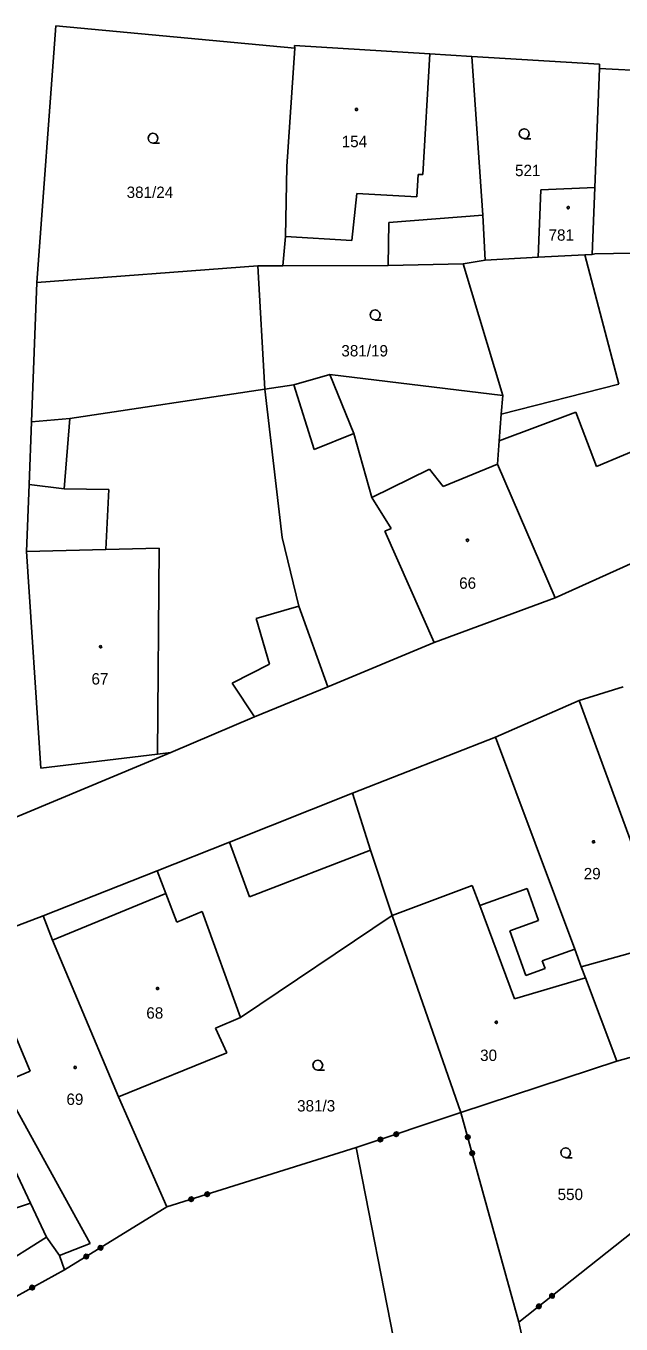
# Model space of a CAD drawing. Extents: x -757994 to -755874, y -1047691 to -1046119.
# Drawn here: x -757585.5 to -757541.1, y -1047173.7 to -1047076.8 of the extents above; entities that cross this region are included whole.
import ezdxf

# ---------------------------------------------------------------- set-up
doc = ezdxf.new("R2010")
doc.units = 0
doc.layers.add('katastrální mapa', color=7, linetype='Continuous')

msp = doc.modelspace()

# ---------------------------------------------------------------- linework, layer by layer
at = {"layer": 'katastrální mapa'}
for p, q in [((-757583.31, -1047076.76), (-757584.71, -1047095.92)), ((-757565.47, -1047078.42), (-757583.31, -1047076.76)), ((-757565.49, -1047078.21), (-757565.47, -1047078.42)), ((-757565.49, -1047078.21), (-757555.39, -1047078.84)), ((-757565.47, -1047078.42), (-757566.07, -1047087.26)), ((-757555.39, -1047078.84), (-757555.93, -1047087.86)), ((-757555.39, -1047078.84), (-757552.27, -1047079.03)), ((-757552.27, -1047079.03), (-757542.74, -1047079.6)), ((-757551.44, -1047090.88), (-757552.27, -1047079.03)), ((-757543.1, -1047088.83), (-757542.75, -1047079.94)), ((-757542.74, -1047079.6), (-757542.75, -1047079.94)), ((-757532.72, -1047080.42), (-757542.75, -1047079.94)), ((-757566.07, -1047087.26), (-757566.18, -1047092.47)), ((-757556.27, -1047087.84), (-757556.36, -1047089.52)), ((-757555.93, -1047087.86), (-757556.27, -1047087.84)), ((-757547.32, -1047094.03), (-757547.13, -1047088.99)), ((-757547.13, -1047088.99), (-757543.1, -1047088.83)), ((-757543.29, -1047093.81), (-757543.1, -1047088.83)), ((-757560.84, -1047089.26), (-757561.21, -1047092.78)), ((-757556.36, -1047089.52), (-757560.84, -1047089.26)), ((-757551.44, -1047090.88), (-757558.46, -1047091.43)), ((-757551.26, -1047094.24), (-757551.44, -1047090.88)), ((-757558.46, -1047091.43), (-757558.5, -1047094.64)), ((-757566.18, -1047092.47), (-757566.37, -1047094.66)), ((-757561.21, -1047092.78), (-757566.18, -1047092.47)), ((-757547.32, -1047094.03), (-757543.84, -1047093.84)), ((-757543.84, -1047093.84), (-757543.29, -1047093.81)), ((-757541.29, -1047103.51), (-757543.84, -1047093.84)), ((-757543.09, -1047093.78), (-757543.29, -1047093.81)), ((-757536.21, -1047093.62), (-757543.09, -1047093.78)), ((-757584.71, -1047095.92), (-757568.22, -1047094.67)), ((-757566.37, -1047094.66), (-757568.22, -1047094.67)), ((-757568.22, -1047094.67), (-757567.7, -1047103.86)), ((-757558.5, -1047094.64), (-757566.37, -1047094.66)), ((-757552.91, -1047094.52), (-757558.5, -1047094.64)), ((-757551.26, -1047094.24), (-757552.91, -1047094.52)), ((-757552.91, -1047094.52), (-757549.96, -1047104.34)), ((-757547.32, -1047094.03), (-757551.26, -1047094.24)), ((-757584.71, -1047095.92), (-757585.12, -1047106.31)), ((-757565.55, -1047103.54), (-757567.7, -1047103.86)), ((-757562.87, -1047102.77), (-757565.55, -1047103.54)), ((-757565.55, -1047103.54), (-757564.03, -1047108.37)), ((-757561.08, -1047107.18), (-757562.87, -1047102.77)), ((-757562.87, -1047102.77), (-757549.96, -1047104.34)), ((-757550.07, -1047105.75), (-757541.29, -1047103.51)), ((-757582.26, -1047106.05), (-757567.7, -1047103.86)), ((-757567.7, -1047103.86), (-757566.42, -1047114.94)), ((-757549.96, -1047104.34), (-757550.07, -1047105.75)), ((-757585.12, -1047106.31), (-757585.3, -1047111)), ((-757585.12, -1047106.31), (-757582.26, -1047106.05)), ((-757582.68, -1047111.31), (-757582.26, -1047106.05)), ((-757544.51, -1047105.59), (-757550.22, -1047107.72)), ((-757550.07, -1047105.75), (-757550.22, -1047107.72)), ((-757544.51, -1047105.59), (-757542.96, -1047109.64)), ((-757542.96, -1047109.64), (-757535.34, -1047106.44)), ((-757564.03, -1047108.37), (-757561.08, -1047107.18)), ((-757559.73, -1047111.95), (-757561.08, -1047107.18)), ((-757550.22, -1047107.72), (-757550.36, -1047109.46)), ((-757555.42, -1047109.84), (-757559.73, -1047111.95)), ((-757554.4, -1047111.14), (-757555.42, -1047109.84)), ((-757550.36, -1047109.46), (-757554.4, -1047111.14)), ((-757550.36, -1047109.46), (-757546.05, -1047119.45)), ((-757585.3, -1047111), (-757585.5, -1047116)), ((-757582.68, -1047111.31), (-757585.3, -1047111)), ((-757579.35, -1047111.36), (-757582.68, -1047111.31)), ((-757579.58, -1047115.84), (-757579.35, -1047111.36)), ((-757559.73, -1047111.95), (-757558.29, -1047114.26)), ((-757529.67, -1047112.06), (-757546.05, -1047119.45)), ((-757566.42, -1047114.94), (-757565.18, -1047120.07)), ((-757558.29, -1047114.26), (-757558.75, -1047114.46)), ((-757558.75, -1047114.46), (-757555.08, -1047122.77)), ((-757579.58, -1047115.84), (-757585.5, -1047116)), ((-757585.5, -1047116), (-757584.43, -1047132.15)), ((-757575.6, -1047115.73), (-757579.58, -1047115.84)), ((-757575.72, -1047131.12), (-757575.6, -1047115.73)), ((-757546.05, -1047119.45), (-757555.08, -1047122.77)), ((-757565.18, -1047120.07), (-757568.35, -1047121)), ((-757568.35, -1047121), (-757567.37, -1047124.41)), ((-757565.18, -1047120.07), (-757563.02, -1047126.09)), ((-757555.08, -1047122.77), (-757563.02, -1047126.09)), ((-757567.37, -1047124.41), (-757570.15, -1047125.82)), ((-757570.15, -1047125.82), (-757568.47, -1047128.34)), ((-757563.02, -1047126.09), (-757568.47, -1047128.34)), ((-757540.98, -1047126.09), (-757544.26, -1047127.12)), ((-757544.26, -1047127.12), (-757550.5, -1047129.84)), ((-757544.26, -1047127.12), (-757539.01, -1047141.42)), ((-757568.47, -1047128.34), (-757574.73, -1047131)), ((-757550.5, -1047129.84), (-757561.18, -1047134.04)), ((-757550.5, -1047129.84), (-757544.58, -1047145.67)), ((-757574.73, -1047131), (-757592.4, -1047138.36)), ((-757584.43, -1047132.15), (-757575.72, -1047131.12)), ((-757575.72, -1047131.12), (-757574.73, -1047131)), ((-757561.18, -1047134.04), (-757570.34, -1047137.69)), ((-757559.83, -1047138.29), (-757561.18, -1047134.04)), ((-757570.34, -1047137.69), (-757575.74, -1047139.82)), ((-757568.85, -1047141.76), (-757570.34, -1047137.69)), ((-757559.83, -1047138.29), (-757568.85, -1047141.76)), ((-757558.21, -1047143.16), (-757559.83, -1047138.29)), ((-757575.74, -1047139.82), (-757584.26, -1047143.18)), ((-757575.74, -1047139.82), (-757575.09, -1047141.52)), ((-757552.23, -1047140.92), (-757558.21, -1047143.16)), ((-757552.23, -1047140.92), (-757551.67, -1047142.42)), ((-757551.67, -1047142.42), (-757548.15, -1047141.15)), ((-757548.15, -1047141.15), (-757547.29, -1047143.53)), ((-757583.54, -1047145.01), (-757575.09, -1047141.52)), ((-757575.09, -1047141.52), (-757574.27, -1047143.65)), ((-757584.26, -1047143.18), (-757589.29, -1047145.09)), ((-757583.54, -1047145.01), (-757584.26, -1047143.18)), ((-757574.27, -1047143.65), (-757572.39, -1047142.85)), ((-757572.39, -1047142.85), (-757569.52, -1047150.77)), ((-757569.52, -1047150.77), (-757558.21, -1047143.16)), ((-757553.08, -1047157.87), (-757558.21, -1047143.16)), ((-757551.67, -1047142.42), (-757549.08, -1047149.39)), ((-757547.29, -1047143.53), (-757549.43, -1047144.3)), ((-757585.21, -1047154.77), (-757589.29, -1047145.09)), ((-757578.64, -1047156.7), (-757583.54, -1047145.01)), ((-757549.43, -1047144.3), (-757548.23, -1047147.63)), ((-757544.1, -1047146.98), (-757537.63, -1047145.17)), ((-757547.01, -1047146.55), (-757544.58, -1047145.67)), ((-757544.58, -1047145.67), (-757544.1, -1047146.98)), ((-757548.23, -1047147.63), (-757546.8, -1047147.12)), ((-757546.8, -1047147.12), (-757547.01, -1047146.55)), ((-757543.78, -1047147.82), (-757544.1, -1047146.98)), ((-757543.78, -1047147.82), (-757549.08, -1047149.39)), ((-757541.46, -1047154.03), (-757543.78, -1047147.82)), ((-757571.39, -1047151.57), (-757569.52, -1047150.77)), ((-757541.46, -1047154.03), (-757530.12, -1047150.9)), ((-757570.55, -1047153.41), (-757571.39, -1047151.57)), ((-757548.75, -1047173.51), (-757521.83, -1047152.14)), ((-757578.64, -1047156.7), (-757570.55, -1047153.41)), ((-757589.05, -1047156.39), (-757585.21, -1047154.77)), ((-757553.08, -1047157.87), (-757541.46, -1047154.03)), ((-757586.95, -1047156.34), (-757580.75, -1047167.65)), ((-757575.01, -1047164.9), (-757578.64, -1047156.7)), ((-757585.19, -1047164.63), (-757588.7, -1047157.2)), ((-757560.89, -1047160.48), (-757553.08, -1047157.87)), ((-757553.08, -1047157.87), (-757548.75, -1047173.51)), ((-757575.01, -1047164.9), (-757560.89, -1047160.48)), ((-757560.89, -1047160.48), (-757553.01, -1047200.67)), ((-757589.11, -1047165.96), (-757585.19, -1047164.63)), ((-757583.99, -1047167.16), (-757585.19, -1047164.63)), ((-757582.65, -1047169.61), (-757575.01, -1047164.9)), ((-757588.96, -1047170.3), (-757583.99, -1047167.16)), ((-757583.04, -1047168.54), (-757583.99, -1047167.16)), ((-757580.75, -1047167.65), (-757583.04, -1047168.54)), ((-757582.65, -1047169.61), (-757583.04, -1047168.54)), ((-757587.83, -1047172.45), (-757582.65, -1047169.61)), ((-757548.75, -1047173.51), (-757545.43, -1047188.81))]:
    msp.add_line(p, q, dxfattribs=at)
for points in [[(-757560.88, -1047082.905), (-757560.83, -1047082.915), (-757560.805, -1047082.96), (-757560.795, -1047082.99), (-757560.805, -1047083.035), (-757560.845, -1047083.07), (-757560.88, -1047083.075), (-757560.925, -1047083.06), (-757560.955, -1047083.03), (-757560.965, -1047082.99), (-757560.955, -1047082.945), (-757560.915, -1047082.91)], [(-757545.08, -1047090.235), (-757545.03, -1047090.245), (-757545.005, -1047090.29), (-757544.995, -1047090.32), (-757545.005, -1047090.365), (-757545.045, -1047090.4), (-757545.08, -1047090.405), (-757545.125, -1047090.39), (-757545.155, -1047090.36), (-757545.165, -1047090.32), (-757545.155, -1047090.275), (-757545.115, -1047090.24)], [(-757552.6, -1047115.065), (-757552.55, -1047115.075), (-757552.525, -1047115.12), (-757552.515, -1047115.15), (-757552.525, -1047115.195), (-757552.565, -1047115.23), (-757552.6, -1047115.235), (-757552.645, -1047115.22), (-757552.675, -1047115.19), (-757552.685, -1047115.15), (-757552.675, -1047115.105), (-757552.635, -1047115.07)], [(-757579.96, -1047123.015), (-757579.91, -1047123.025), (-757579.885, -1047123.07), (-757579.875, -1047123.1), (-757579.885, -1047123.145), (-757579.925, -1047123.18), (-757579.96, -1047123.185), (-757580.005, -1047123.17), (-757580.035, -1047123.14), (-757580.045, -1047123.1), (-757580.035, -1047123.055), (-757579.995, -1047123.02)], [(-757543.18, -1047137.575), (-757543.13, -1047137.585), (-757543.105, -1047137.63), (-757543.095, -1047137.66), (-757543.105, -1047137.705), (-757543.145, -1047137.74), (-757543.18, -1047137.745), (-757543.225, -1047137.73), (-757543.255, -1047137.7), (-757543.265, -1047137.66), (-757543.255, -1047137.615), (-757543.215, -1047137.58)], [(-757575.71, -1047148.525), (-757575.66, -1047148.535), (-757575.635, -1047148.58), (-757575.625, -1047148.61), (-757575.635, -1047148.655), (-757575.675, -1047148.69), (-757575.71, -1047148.695), (-757575.755, -1047148.68), (-757575.785, -1047148.65), (-757575.795, -1047148.61), (-757575.785, -1047148.565), (-757575.745, -1047148.53)], [(-757550.44, -1047151.045), (-757550.39, -1047151.055), (-757550.365, -1047151.1), (-757550.355, -1047151.13), (-757550.365, -1047151.175), (-757550.405, -1047151.21), (-757550.44, -1047151.215), (-757550.485, -1047151.2), (-757550.515, -1047151.17), (-757550.525, -1047151.13), (-757550.515, -1047151.085), (-757550.475, -1047151.05)], [(-757581.87, -1047154.415), (-757581.82, -1047154.425), (-757581.795, -1047154.47), (-757581.785, -1047154.5), (-757581.795, -1047154.545), (-757581.835, -1047154.58), (-757581.87, -1047154.585), (-757581.915, -1047154.57), (-757581.945, -1047154.54), (-757581.955, -1047154.5), (-757581.945, -1047154.455), (-757581.905, -1047154.42)]]:
    msp.add_lwpolyline(points, close=True, dxfattribs=at)
for points in [[(-757576.05, -1047085.51), (-757576.24, -1047085.46), (-757576.375, -1047085.325), (-757576.425, -1047085.14), (-757576.375, -1047084.955), (-757576.24, -1047084.82), (-757576.055, -1047084.77), (-757575.87, -1047084.82), (-757575.735, -1047084.955), (-757575.685, -1047085.145), (-757575.735, -1047085.335), (-757575.87, -1047085.47), (-757576.06, -1047085.52), (-757575.56, -1047085.52)], [(-757548.35, -1047085.17), (-757548.54, -1047085.12), (-757548.675, -1047084.985), (-757548.725, -1047084.8), (-757548.675, -1047084.615), (-757548.54, -1047084.48), (-757548.355, -1047084.43), (-757548.17, -1047084.48), (-757548.035, -1047084.615), (-757547.985, -1047084.805), (-757548.035, -1047084.995), (-757548.17, -1047085.13), (-757548.36, -1047085.18), (-757547.86, -1047085.18)], [(-757559.48, -1047098.7), (-757559.67, -1047098.65), (-757559.805, -1047098.515), (-757559.855, -1047098.33), (-757559.805, -1047098.145), (-757559.67, -1047098.01), (-757559.485, -1047097.96), (-757559.3, -1047098.01), (-757559.165, -1047098.145), (-757559.115, -1047098.335), (-757559.165, -1047098.525), (-757559.3, -1047098.66), (-757559.49, -1047098.71), (-757558.99, -1047098.71)], [(-757563.76, -1047154.7), (-757563.95, -1047154.65), (-757564.085, -1047154.515), (-757564.135, -1047154.33), (-757564.085, -1047154.145), (-757563.95, -1047154.01), (-757563.765, -1047153.96), (-757563.58, -1047154.01), (-757563.445, -1047154.145), (-757563.395, -1047154.335), (-757563.445, -1047154.525), (-757563.58, -1047154.66), (-757563.77, -1047154.71), (-757563.27, -1047154.71)], [(-757559.077, -1047159.706), (-757558.957, -1047159.766), (-757558.914, -1047159.894), (-757558.974, -1047160.014), (-757559.102, -1047160.057), (-757559.222, -1047159.997), (-757559.265, -1047159.869), (-757559.205, -1047159.749), (-757559.077, -1047159.706), (-757559.075, -1047159.726), (-757559.189, -1047159.764), (-757559.214, -1047159.815), (-757559.025, -1047159.751), (-757558.974, -1047159.777), (-757559.24, -1047159.866), (-757559.227, -1047159.904), (-757558.961, -1047159.815), (-757558.949, -1047159.853), (-757559.214, -1047159.941), (-757559.202, -1047159.979), (-757558.936, -1047159.891), (-757558.961, -1047159.941), (-757559.151, -1047160.005), (-757559.1, -1047160.03), (-757558.987, -1047159.992)], [(-757557.892, -1047159.309), (-757557.771, -1047159.369), (-757557.729, -1047159.497), (-757557.789, -1047159.617), (-757557.917, -1047159.66), (-757558.037, -1047159.6), (-757558.08, -1047159.472), (-757558.02, -1047159.352), (-757557.892, -1047159.309), (-757557.9, -1047159.333), (-757558.013, -1047159.371), (-757558.039, -1047159.421), (-757557.849, -1047159.358), (-757557.798, -1047159.383), (-757558.064, -1047159.472), (-757558.051, -1047159.51), (-757557.786, -1047159.421), (-757557.773, -1047159.459), (-757558.038, -1047159.548), (-757558.026, -1047159.586), (-757557.76, -1047159.497), (-757557.785, -1047159.548), (-757557.975, -1047159.611), (-757557.924, -1047159.636), (-757557.811, -1047159.598)], [(-757552.401, -1047159.721), (-757552.468, -1047159.838), (-757552.598, -1047159.874), (-757552.714, -1047159.808), (-757552.75, -1047159.678), (-757552.684, -1047159.561), (-757552.554, -1047159.525), (-757552.437, -1047159.591), (-757552.401, -1047159.721), (-757552.422, -1047159.722), (-757552.454, -1047159.606), (-757552.503, -1047159.578), (-757552.45, -1047159.771), (-757552.478, -1047159.82), (-757552.552, -1047159.55), (-757552.591, -1047159.561), (-757552.516, -1047159.831), (-757552.555, -1047159.841), (-757552.629, -1047159.571), (-757552.668, -1047159.582), (-757552.593, -1047159.852), (-757552.643, -1047159.824), (-757552.696, -1047159.631), (-757552.724, -1047159.681), (-757552.692, -1047159.796)], [(-757552.068, -1047160.926), (-757552.135, -1047161.043), (-757552.265, -1047161.079), (-757552.382, -1047161.012), (-757552.418, -1047160.882), (-757552.351, -1047160.765), (-757552.221, -1047160.73), (-757552.104, -1047160.796), (-757552.068, -1047160.926), (-757552.092, -1047160.917), (-757552.124, -1047160.801), (-757552.173, -1047160.773), (-757552.119, -1047160.966), (-757552.147, -1047161.015), (-757552.222, -1047160.745), (-757552.261, -1047160.756), (-757552.186, -1047161.026), (-757552.224, -1047161.037), (-757552.299, -1047160.767), (-757552.338, -1047160.777), (-757552.263, -1047161.047), (-757552.312, -1047161.019), (-757552.366, -1047160.826), (-757552.393, -1047160.876), (-757552.361, -1047160.991)], [(-757545.26, -1047161.23), (-757545.45, -1047161.18), (-757545.585, -1047161.045), (-757545.635, -1047160.86), (-757545.585, -1047160.675), (-757545.45, -1047160.54), (-757545.265, -1047160.49), (-757545.08, -1047160.54), (-757544.945, -1047160.675), (-757544.895, -1047160.865), (-757544.945, -1047161.055), (-757545.08, -1047161.19), (-757545.27, -1047161.24), (-757544.77, -1047161.24)], [(-757573.183, -1047164.16), (-757573.064, -1047164.222), (-757573.023, -1047164.351), (-757573.086, -1047164.47), (-757573.214, -1047164.511), (-757573.333, -1047164.448), (-757573.374, -1047164.319), (-757573.311, -1047164.2), (-757573.183, -1047164.16), (-757573.181, -1047164.181), (-757573.296, -1047164.216), (-757573.322, -1047164.267), (-757573.131, -1047164.207), (-757573.081, -1047164.233), (-757573.348, -1047164.317), (-757573.336, -1047164.355), (-757573.069, -1047164.271), (-757573.057, -1047164.31), (-757573.324, -1047164.393), (-757573.313, -1047164.431), (-757573.045, -1047164.348), (-757573.072, -1047164.398), (-757573.262, -1047164.457), (-757573.212, -1047164.484), (-757573.098, -1047164.448)], [(-757571.989, -1047163.787), (-757571.87, -1047163.849), (-757571.83, -1047163.978), (-757571.892, -1047164.097), (-757572.021, -1047164.138), (-757572.14, -1047164.075), (-757572.181, -1047163.946), (-757572.118, -1047163.827), (-757571.989, -1047163.787), (-757571.998, -1047163.811), (-757572.112, -1047163.846), (-757572.139, -1047163.897), (-757571.948, -1047163.837), (-757571.898, -1047163.863), (-757572.165, -1047163.947), (-757572.153, -1047163.985), (-757571.886, -1047163.901), (-757571.874, -1047163.94), (-757572.141, -1047164.023), (-757572.129, -1047164.061), (-757571.862, -1047163.978), (-757571.888, -1047164.028), (-757572.079, -1047164.087), (-757572.029, -1047164.114), (-757571.914, -1047164.078)], [(-757581.061, -1047168.442), (-757580.931, -1047168.473), (-757580.86, -1047168.588), (-757580.891, -1047168.719), (-757581.006, -1047168.79), (-757581.137, -1047168.759), (-757581.207, -1047168.644), (-757581.176, -1047168.513), (-757581.061, -1047168.442), (-757581.055, -1047168.462), (-757581.157, -1047168.525), (-757581.17, -1047168.58), (-757581, -1047168.475), (-757580.945, -1047168.488), (-757581.183, -1047168.635), (-757581.162, -1047168.669), (-757580.924, -1047168.522), (-757580.903, -1047168.556), (-757581.142, -1047168.703), (-757581.121, -1047168.737), (-757580.882, -1047168.59), (-757580.895, -1047168.645), (-757581.066, -1047168.75), (-757581.01, -1047168.763), (-757580.908, -1047168.7)], [(-757579.997, -1047167.787), (-757579.866, -1047167.818), (-757579.796, -1047167.933), (-757579.827, -1047168.064), (-757579.942, -1047168.134), (-757580.072, -1047168.103), (-757580.143, -1047167.988), (-757580.112, -1047167.858), (-757579.997, -1047167.787), (-757579.999, -1047167.812), (-757580.101, -1047167.875), (-757580.115, -1047167.93), (-757579.944, -1047167.825), (-757579.889, -1047167.838), (-757580.128, -1047167.985), (-757580.107, -1047168.019), (-757579.868, -1047167.872), (-757579.847, -1047167.906), (-757580.086, -1047168.053), (-757580.065, -1047168.087), (-757579.826, -1047167.94), (-757579.839, -1047167.995), (-757580.01, -1047168.1), (-757579.955, -1047168.113), (-757579.852, -1047168.05)], [(-757585.088, -1047170.764), (-757584.959, -1047170.801), (-757584.894, -1047170.92), (-757584.932, -1047171.049), (-757585.05, -1047171.114), (-757585.179, -1047171.076), (-757585.244, -1047170.958), (-757585.206, -1047170.829), (-757585.088, -1047170.764), (-757585.092, -1047170.789), (-757585.197, -1047170.846), (-757585.213, -1047170.901), (-757585.037, -1047170.804), (-757584.983, -1047170.82), (-757585.228, -1047170.955), (-757585.209, -1047170.99), (-757584.964, -1047170.855), (-757584.944, -1047170.89), (-757585.19, -1047171.025), (-757585.171, -1047171.06), (-757584.925, -1047170.925), (-757584.941, -1047170.98), (-757585.116, -1047171.076), (-757585.062, -1047171.092), (-757584.957, -1047171.034)], [(-757546.331, -1047171.386), (-757546.198, -1047171.401), (-757546.114, -1047171.507), (-757546.129, -1047171.64), (-757546.235, -1047171.724), (-757546.369, -1047171.709), (-757546.453, -1047171.603), (-757546.437, -1047171.47), (-757546.331, -1047171.386), (-757546.331, -1047171.411), (-757546.425, -1047171.485), (-757546.431, -1047171.542), (-757546.275, -1047171.417), (-757546.218, -1047171.424), (-757546.438, -1047171.598), (-757546.413, -1047171.629), (-757546.193, -1047171.455), (-757546.169, -1047171.486), (-757546.388, -1047171.66), (-757546.363, -1047171.692), (-757546.144, -1047171.518), (-757546.15, -1047171.574), (-757546.307, -1047171.698), (-757546.251, -1047171.705), (-757546.157, -1047171.63)], [(-757547.31, -1047172.163), (-757547.177, -1047172.178), (-757547.093, -1047172.284), (-757547.108, -1047172.418), (-757547.214, -1047172.501), (-757547.348, -1047172.486), (-757547.432, -1047172.38), (-757547.416, -1047172.247), (-757547.31, -1047172.163), (-757547.302, -1047172.182), (-757547.396, -1047172.256), (-757547.402, -1047172.313), (-757547.246, -1047172.188), (-757547.19, -1047172.195), (-757547.409, -1047172.369), (-757547.384, -1047172.4), (-757547.165, -1047172.226), (-757547.14, -1047172.257), (-757547.359, -1047172.431), (-757547.334, -1047172.463), (-757547.115, -1047172.289), (-757547.121, -1047172.345), (-757547.278, -1047172.469), (-757547.222, -1047172.476), (-757547.128, -1047172.401)]]:
    msp.add_lwpolyline(points, dxfattribs=at)

# ---------------------------------------------------------------- texts
for s, p in [('154', (-757561.976, -1047085.81)), ('521', (-757549.043, -1047087.97)), ('381/24', (-757578.021, -1047089.6)), ('781', (-757546.541, -1047092.79)), ('381/19', (-757562, -1047101.43)), ('66', (-757553.212, -1047118.77)), ('67', (-757580.642, -1047125.92)), ('29', (-757543.919, -1047140.46)), ('68', (-757576.552, -1047150.86)), ('30', (-757551.649, -1047154.02)), ('69', (-757582.512, -1047157.3)), ('381/3', (-757565.303, -1047157.79)), ('550', (-757545.867, -1047164.4))]:
    msp.add_text(s, height=0.85, dxfattribs=at).set_placement(p)

doc.saveas('drawing.dxf')
